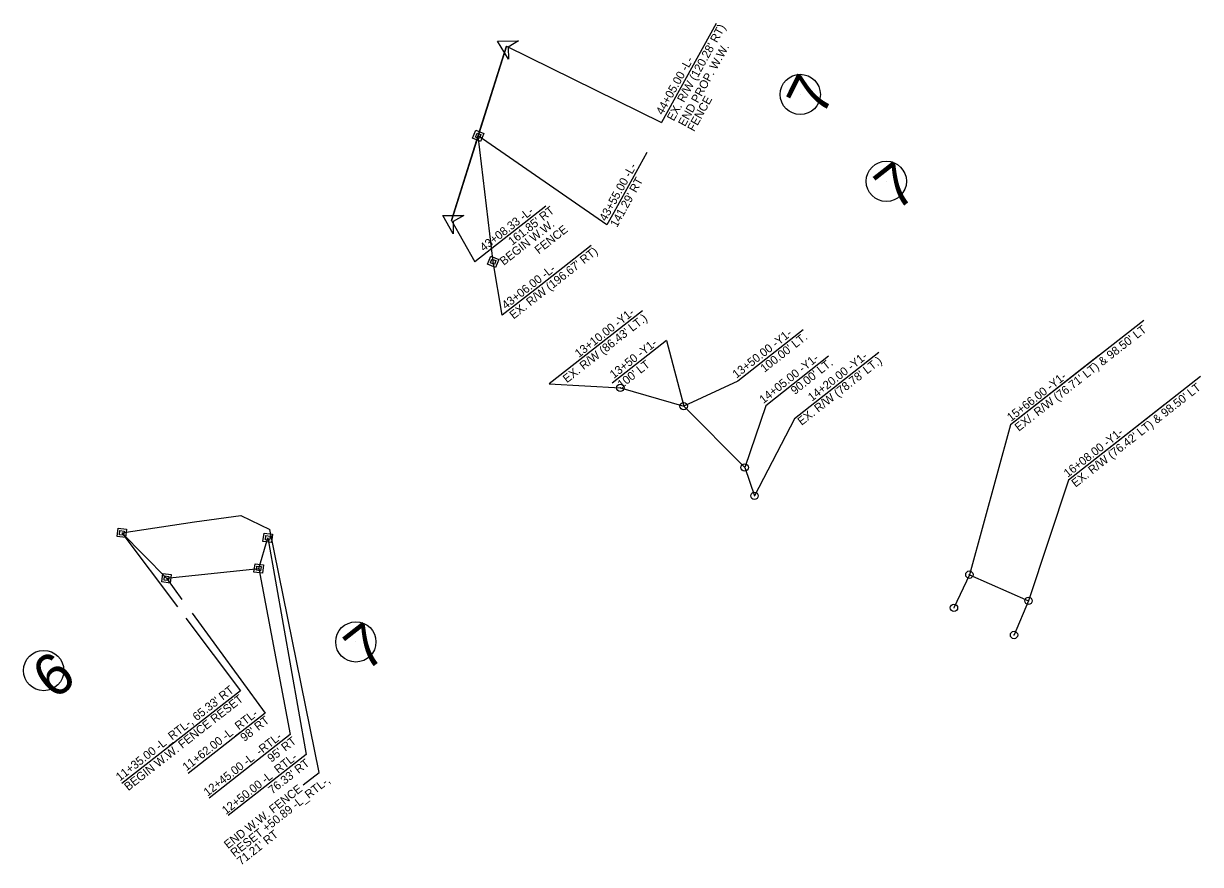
# Model space of a CAD drawing. Extents: x 2175623 to 2194100, y 76458 to 87202.
# Drawn here: x 2176486 to 2177187, y 76941 to 77442 of the extents above; entities that cross this region are included whole.
import ezdxf

# ---------------------------------------------------------------- set-up
doc = ezdxf.new("R2010")
doc.units = 0
for name, color, linetype in [('Exist Plan Preparation Watershed Yellow', 7, 'Continuous'), ('Exist Property Iron Pin CELL', 7, 'Continuous'), ('Prop Drainage Structure Box Number Symbol CELL', 7, 'Continuous'), ('Prop Drainage Structure Drop Inlet Grate 840 16 CELL', 7, 'Continuous'), ('Prop Drainage Structure Headwall CELL', 7, 'Continuous'), ('Prop Drainage Structure Pipe RCP 36in Class IV', 7, 'Continuous'), ('Prop Drainage Structure Pipe RCP 42in Class IV', 7, 'Continuous'), ('Prop Drainage Structure Pipe RCP 60in Class IV', 7, 'Continuous'), ('Prop Drainage Structure Pipe Removal Label', 7, 'Continuous'), ('Prop Drainage Structure Plot Symbol 20 Scale', 7, 'Continuous'), ('Prop Drainage Structure Plot Symbol 50 Scale', 7, 'Continuous'), ('Prop Earthen Structure Base Ditch Special Lateral Detail Label', 7, 'Continuous'), ('Prop Earthen Structure V Ditch Special Lateral Detail Label', 7, 'Continuous'), ('Prop Erosion Rip Rap Pad at Outlet Label', 7, 'Continuous'), ('Prop Plan Preparation Crest Label', 7, 'Continuous'), ('Prop Plan Preparation Sag', 7, 'Continuous'), ('Prop Plan Preparation Sag Label', 7, 'Continuous'), ('Scratch_Level_3', 7, 'Continuous')]:
    doc.layers.add(name, color=color, linetype=linetype)

# ---------------------------------------------------------------- blocks, each defined once
blk = doc.blocks.new('ROW Marker Permanent Easement-E')
at = {"layer": 'Prop Earthen Structure Base Ditch Special Lateral Detail Label'}
for points in [[(0, 0.072), (0.072, 0), (0, -0.072), (-0.072, 0)], [(0, 0.036), (0.036, 0), (0, -0.036), (-0.036, 0)]]:
    blk.add_lwpolyline(points, close=True, dxfattribs=at)
at = {"layer": 'Prop Plan Preparation Crest Label'}
blk.add_line((0, 0), (0, 0), dxfattribs=at)

msp = doc.modelspace()

# ---------------------------------------------------------------- linework, layer by layer
at = {"layer": 'Exist Plan Preparation Watershed Yellow'}
for p, q in [((2176768.31, 77431.89), (2176780.79, 77432.16)), ((2176774.76, 77421.2), (2176768.31, 77431.89)), ((2176780.79, 77432.16), (2176774.62, 77428.42)), ((2176774.62, 77428.42), (2176774.76, 77421.2)), ((2176741.91, 77317.19), (2176735.71, 77328.02)), ((2176735.71, 77328.02), (2176748.19, 77328)), ((2176741.93, 77324.4), (2176741.91, 77317.19)), ((2176748.19, 77328), (2176741.93, 77324.4))]:
    msp.add_line(p, q, dxfattribs=at)
at = {"layer": 'Exist Property Iron Pin CELL'}
for centre, radius in [((2176841.5, 77225.27), 2.2), ((2176841.5, 77225.27), 0.0707), ((2176879.24, 77214.4), 2.2), ((2176879.24, 77214.4), 0.0707), ((2176915.61, 77177.81), 2.2), ((2176915.61, 77177.81), 0.0707), ((2176921.4, 77160.89), 2.2), ((2176921.4, 77160.89), 0.0707), ((2177049.52, 77113.9), 2.2), ((2177049.52, 77113.9), 0.0707), ((2177084.74, 77098.29), 2.2), ((2177040.34, 77094.15), 2.2), ((2177040.34, 77094.15), 0.0707), ((2177084.74, 77098.29), 0.0707), ((2177076.15, 77077.95), 2.2), ((2177076.15, 77077.95), 0.0707)]:
    msp.add_circle(centre, radius, dxfattribs=at)
at = {"layer": 'Prop Drainage Structure Box Number Symbol CELL'}
for p, q in [((2176948.73, 77400.19), (2176948.73, 77400.19)), ((2177000.01, 77348.4), (2177000.01, 77348.4)), ((2176683.85, 77073.83), (2176683.85, 77073.83)), ((2176497.79, 77056.75), (2176497.79, 77056.75))]:
    msp.add_line(p, q, dxfattribs=at)
for centre in [(2176948.73, 77400.19), (2177000.01, 77348.4), (2176683.85, 77073.83), (2176497.79, 77056.75)]:
    msp.add_circle(centre, 12, dxfattribs=at)
at = {"layer": 'Prop Drainage Structure Drop Inlet Grate 840 16 CELL'}
for p, q in [((2176544.38, 77138.82), (2176577.47, 77094.74)), ((2176631.34, 77135.83), (2176654.17, 77006.78)), ((2176625.98, 77117.6), (2176644.76, 77018.7)), ((2176571.01, 77111.77), (2176580.22, 77099.19)), ((2176582.5, 77088.04), (2176615.07, 77044.67)), ((2176586.23, 77090.97), (2176629.82, 77031.39)), ((2176615.07, 77044.67), (2176544.47, 76989.33)), ((2176629.82, 77031.39), (2176583.97, 76995.44)), ((2176644.76, 77018.7), (2176596.34, 76980.74)), ((2176654.17, 77006.78), (2176607.69, 76970.34))]:
    msp.add_line(p, q, dxfattribs=at)
at = {"layer": 'Prop Drainage Structure Headwall CELL'}
for p, q in [((2176857.24, 77365.57), (2176837.53, 77329.9)), ((2176824.16, 77310.2), (2176794.03, 77286.58))]:
    msp.add_line(p, q, dxfattribs=at)
for points in [[(2176837.53, 77329.9), (2176833.47, 77322.54), (2176756.77, 77375.52)], [(2176794.03, 77286.58), (2176771.16, 77268.65), (2176765.69, 77300.42)]]:
    msp.add_lwpolyline(points, dxfattribs=at)
at = {"layer": 'Prop Drainage Structure Pipe RCP 36in Class IV'}
for p, q in [((2176854.66, 77271.2), (2176799.09, 77227.64)), ((2176950.53, 77259.93), (2176911.44, 77229.29)), ((2176868.97, 77253.5), (2176836.63, 77228.15)), ((2176868.97, 77253.5), (2176879.24, 77214.4)), ((2176995.65, 77246.31), (2176945.24, 77206.8)), ((2176965.48, 77244.14), (2176928.15, 77214.48)), ((2176799.09, 77227.64), (2176841.5, 77225.27)), ((2176911.44, 77229.29), (2176879.24, 77214.4)), ((2176928.15, 77214.48), (2176915.61, 77177.81)), ((2176945.24, 77206.8), (2176921.4, 77160.89))]:
    msp.add_line(p, q, dxfattribs=at)
at = {"layer": 'Prop Drainage Structure Pipe RCP 42in Class IV'}
for p, q in [((2177049.52, 77113.9), (2177040.34, 77094.15)), ((2177049.52, 77113.9), (2177084.74, 77098.29)), ((2177084.74, 77098.29), (2177076.15, 77077.95))]:
    msp.add_line(p, q, dxfattribs=at)
at = {"layer": 'Prop Drainage Structure Pipe RCP 60in Class IV'}
for p, q in [((2177126.77, 77244.49), (2177074.1, 77203.2)), ((2177166.26, 77215.57), (2177108.52, 77170.32))]:
    msp.add_line(p, q, dxfattribs=at)
for points in [[(2177153.51, 77265.45), (2177074.1, 77203.2), (2177049.52, 77113.9)], [(2177187.26, 77232.04), (2177108.52, 77170.32), (2177084.74, 77098.29)]]:
    msp.add_lwpolyline(points, dxfattribs=at)
at = {"layer": 'Prop Drainage Structure Pipe Removal Label'}
for p, q in [((2176662.04, 76996.06), (2176632.56, 77140.84)), ((2176652.44, 76988.53), (2176662.04, 76996.06))]:
    msp.add_line(p, q, dxfattribs=at)
at = {"layer": 'Prop Drainage Structure Plot Symbol 20 Scale'}
for p, q in [((2176544.38, 77138.82), (2176571.01, 77111.77)), ((2176625.98, 77117.6), (2176631.34, 77135.83)), ((2176571.01, 77111.77), (2176625.98, 77117.6))]:
    msp.add_line(p, q, dxfattribs=at)
at = {"layer": 'Prop Drainage Structure Plot Symbol 50 Scale'}
msp.add_line((2176765.69, 77300.42), (2176756.77, 77375.52), dxfattribs=at)
at = {"layer": 'Prop Earthen Structure V Ditch Special Lateral Detail Label'}
for p, q in [((2176758.02, 77379.51), (2176773.57, 77428.99)), ((2176740.9, 77325), (2176758.02, 77379.51))]:
    msp.add_line(p, q, dxfattribs=at)
at = {"layer": 'Prop Plan Preparation Sag'}
for p, q in [((2176898.53, 77442.46), (2176865.98, 77383.5)), ((2176773.57, 77428.99), (2176865.98, 77383.5)), ((2176797.15, 77333.61), (2176754.86, 77300.46)), ((2176740.9, 77325), (2176754.86, 77300.46))]:
    msp.add_line(p, q, dxfattribs=at)
at = {"layer": 'Prop Plan Preparation Sag Label'}
for p, q in [((2176841.5, 77225.27), (2176879.24, 77214.4)), ((2176879.24, 77214.4), (2176915.61, 77177.81)), ((2176915.61, 77177.81), (2176921.4, 77160.89))]:
    msp.add_line(p, q, dxfattribs=at)
at = {"layer": 'Scratch_Level_3'}
msp.add_line((2176773.57, 77428.99), (2176740.9, 77325), dxfattribs=at)
msp.add_lwpolyline([(2176544.38, 77138.82), (2176587.61, 77145.5), (2176615.26, 77149.13), (2176632.56, 77140.84)], dxfattribs=at)

# ---------------------------------------------------------------- block references
at = {"layer": 'Prop Plan Preparation Sag Label'}
for p, xscale, yscale, rotation in [((2176756.77, 77375.52), 49.99999999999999, 50.00000000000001, -156.87942851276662), ((2176765.69, 77300.42), 49.99999999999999, 50.00000000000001, -156.87942851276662), ((2176544.38, 77138.82), 50, 50, -141.9089540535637), ((2176631.34, 77135.83), 50, 50, -141.9089540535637), ((2176625.98, 77117.6), 50, 50, -141.9089540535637), ((2176571.01, 77111.77), 50, 50, -141.9089540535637)]:
    msp.add_blockref('ROW Marker Permanent Easement-E', p, dxfattribs=dict(at, xscale=xscale, yscale=yscale, rotation=rotation))

# ---------------------------------------------------------------- texts
at = {"layer": 'Prop Drainage Structure Drop Inlet Grate 840 16 CELL'}
for s, p in [("11+35.00 -L_RTL-, 65.33' RT ", (2176543.22, 76990.58)), ('11+62.00 -L_RTL- ', (2176582.96, 76996.62)), ("98' RT", (2176617.43, 77014.12)), ('12+45.00 -L_-RTL- ', (2176595.53, 76981.53)), ("95' RT", (2176633.51, 77001.78)), ('12+50.00 -L_RTL-', (2176606.45, 76970.69)), ("76.33' RT", (2176634.08, 76982.82))]:
    msp.add_text(s, height=5, rotation=38.0951, dxfattribs=at).set_placement(p)
at = {"layer": 'Prop Drainage Structure Headwall CELL'}
for s, rotation, p in [('43+55.00 -L-', 61.07333, (2176832.94, 77324.17)), ("141.29' RT", 61.07333, (2176839.5, 77320.55)), ("EX. R/W (196.67' RT)", 38.0951, (2176777.88, 77265.98)), ('43+06.00 -L-', 38.0951, (2176773.26, 77271.88))]:
    msp.add_text(s, height=5, rotation=rotation, dxfattribs=at).set_placement(p)
at = {"layer": 'Prop Drainage Structure Pipe RCP 36in Class IV'}
for s, rotation, p in [("EX. R/W (86.43' LT.)", 38.0951, (2176809.68, 77227.96)), ('13+10.00 -Y1-', 38.0951, (2176816.79, 77243.06)), ('13+50.00 -Y1-', 38.09105, (2176910.72, 77230.69)), ("100.00' LT.", 38.09105, (2176927.38, 77234.22)), ('13+50 -Y1-', 38.0951, (2176837.62, 77230.57)), ("100' LT", 38.0951, (2176842.25, 77224.67)), ('14+05.00 -Y1-', 38.46797, (2176926.77, 77215.61)), ("90.00' LT.", 38.46797, (2176945.57, 77220.97)), ("EX. R/W (78.78' LT.)", 38.09105, (2176949.54, 77202.61)), ('14+20.00 -Y1-', 38.09105, (2176955.71, 77216.98))]:
    msp.add_text(s, height=5, rotation=rotation, dxfattribs=at).set_placement(p)
at = {"layer": 'Prop Drainage Structure Pipe RCP 60in Class IV'}
for s, p in [("EX/. R/W (76.71' LT) & 98.50' LT", (2177078.98, 77199.08)), ('15+66.00 -Y1-', (2177074.35, 77204.98)), ("EX. R/W (76.42' LT) & 98.50' LT", (2177112.81, 77165.74)), ('16+08.00 -Y1-', (2177108.18, 77171.64))]:
    msp.add_text(s, height=5, rotation=38.09105, dxfattribs=at).set_placement(p)
at = {"layer": 'Prop Drainage Structure Pipe Removal Label'}
for s, rotation, p in [('END PROP. W.W.', 61.07333, (2176880, 77380.69)), ('FENCE ', 61.07333, (2176885.47, 77377.67)), ('BEGIN W.W.', 38.09105, (2176772.04, 77298.02)), ('FENCE', 38.09105, (2176792.85, 77304.8)), ('BEGIN W.W. FENCE RESET', 38.0951, (2176548.24, 76984.8)), ('END W.W. FENCE', 38.0951, (2176607.68, 76950.24)), ('RESET +50.89 -L_RTL-,', 38.0951, (2176611.54, 76945.33)), ("71.21' RT", 38.0951, (2176615.39, 76940.41))]:
    msp.add_text(s, height=5, rotation=rotation, dxfattribs=at).set_placement(p)
at = {"layer": 'Prop Erosion Rip Rap Pad at Outlet Label'}
for s, rotation, p in [('7', 63.56732, (2176961.9, 77386.37)), ('7', 38.09105, (2177005.96, 77330.26)), ('7', 38.0951, (2176689.8, 77055.68)), ('6', 38.0951, (2176503.9, 77038.74))]:
    msp.add_text(s, height=25, rotation=rotation, dxfattribs=at).set_placement(p)
at = {"layer": 'Prop Plan Preparation Sag'}
for s, rotation, p in [("EX. R/W (120.28' RT)", 61.10212, (2176873.31, 77383.95)), ('44+05.00 -L- ', 61.10212, (2176866.74, 77387.58)), ('43+08.33 -L- ', 38.09105, (2176760.21, 77306.3)), ("161.85' RT", 38.09105, (2176777.05, 77309.97))]:
    msp.add_text(s, height=5, rotation=rotation, dxfattribs=at).set_placement(p)

doc.saveas('drawing.dxf')
